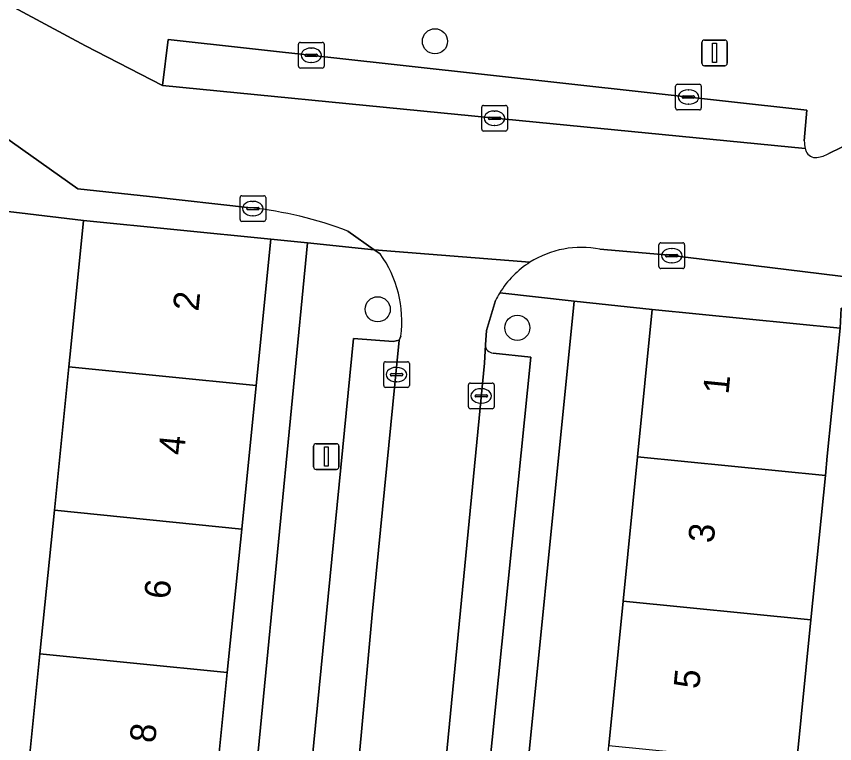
# Model space of a CAD drawing. Extents: x 162250 to 162661, y 380743 to 381606.
# Drawn here: x 162307.32 to 162339.15, y 380878.59 to 380906.87 of the extents above; entities that cross this region are included whole.
import ezdxf

# ---------------------------------------------------------------- set-up
doc = ezdxf.new("R2010")
doc.units = 0
for name, color, linetype in [('IMGEO_Boom', 7, 'Continuous'), ('IMGEO_Erf', 7, 'Continuous'), ('IMGEO_Kolk', 7, 'Continuous'), ('IMGEO_Lichtmast', 7, 'Continuous'), ('IMGEO_Muur', 7, 'Continuous'), ('IMGEO_Pand', 7, 'Continuous'), ('IMGEO_Pand_nummerreeks', 7, 'Continuous'), ('IMGEO_Parkeervlak_open', 7, 'Continuous'), ('IMGEO_Rijbaan_lokaal_open', 7, 'Continuous'), ('IMGEO_Rioolput', 7, 'Continuous'), ('IMGEO_Voetpad_open', 7, 'Continuous')]:
    doc.layers.add(name, color=color, linetype=linetype)

msp = doc.modelspace()

# ---------------------------------------------------------------- linework, layer by layer
at = {"layer": 'IMGEO_Boom'}
for centre in [(162323.604, 380905.904), (162321.376, 380895.484), (162326.808, 380894.764)]:
    msp.add_circle(centre, 0.489, dxfattribs=at)
at = {"layer": 'IMGEO_Erf'}
msp.add_lwpolyline([(162307.682, 380876.513), (162308.241, 380882.089), (162308.8, 380887.667), (162309.359, 380893.244), (162309.435, 380893.999), (162309.931, 380898.942), (162307.447, 380899.233), (162299.23, 380900.181), (162298.807, 380896.512), (162302.633, 380896.065), (162302.385, 380893.943), (162302.081, 380891.349), (162298.255, 380891.796), (162297.549, 380885.372), (162301.375, 380884.925), (162301.127, 380882.802), (162300.823, 380880.209), (162296.997, 380880.656), (162296.291, 380874.233)], dxfattribs=at)
for points in [[(162317.217, 380898.211), (162316.646, 380892.514), (162316.086, 380886.937), (162315.527, 380881.36), (162314.968, 380875.783), (162314.409, 380870.206), (162313.849, 380864.627), (162313.289, 380859.043), (162312.729, 380853.459), (162312.169, 380847.873), (162311.609, 380842.288), (162311.049, 380836.704), (162310.497, 380831.191), (162309.933, 380825.574), (162309.37, 380819.961), (162308.808, 380814.349), (162308.245, 380808.736), (162307.67, 380803.003), (162309.116, 380802.856), (162315.15, 380861.984), (162318.65, 380898.061)], [(162331.483, 380889.744), (162332.054, 380895.474), (162329.014, 380895.802), (162326.75, 380873.094), (162329.792, 380872.791), (162330.363, 380878.521), (162330.923, 380884.132)], [(162349.956, 380885.449), (162346.117, 380885.769), (162346.325, 380888.261), (162346.512, 380890.503), (162350.351, 380890.183), (162350.689, 380894.244), (162339.398, 380895.532), (162339.361, 380894.746), (162338.865, 380889.771), (162338.79, 380889.014), (162338.23, 380883.402), (162337.67, 380877.791), (162337.099, 380872.063), (162348.708, 380870.908), (162348.984, 380874.212), (162345.145, 380874.532), (162345.353, 380877.023), (162345.54, 380879.266), (162349.379, 380878.946)]]:
    msp.add_lwpolyline(points, close=True, dxfattribs=at)
at = {"layer": 'IMGEO_Kolk'}
for p, q in [((162318.294, 380904.936), (162318.294, 380905.788)), ((162318.369, 380905.862), (162319.221, 380905.862)), ((162319.295, 380905.788), (162319.295, 380904.936)), ((162318.782, 380905.642), (162318.807, 380905.642)), ((162318.553, 380905.356), (162318.553, 380905.368)), ((162318.991, 380905.319), (162318.593, 380905.319)), ((162318.596, 380905.405), (162318.994, 380905.405)), ((162319.037, 380905.368), (162319.037, 380905.356)), ((162319.221, 380904.862), (162318.369, 380904.862)), ((162318.805, 380905.082), (162318.78, 380905.082)), ((162333.036, 380904.237), (162333.888, 380904.237)), ((162332.961, 380903.311), (162332.961, 380904.163)), ((162333.449, 380904.017), (162333.474, 380904.017)), ((162333.962, 380904.163), (162333.962, 380903.311)), ((162333.22, 380903.731), (162333.22, 380903.743)), ((162333.658, 380903.694), (162333.26, 380903.694)), ((162333.263, 380903.78), (162333.661, 380903.78)), ((162333.704, 380903.743), (162333.704, 380903.731)), ((162333.888, 380903.237), (162333.036, 380903.237)), ((162333.472, 380903.457), (162333.447, 380903.457)), ((162316.022, 380898.974), (162316.022, 380899.826)), ((162316.097, 380899.9), (162316.949, 380899.9)), ((162317.023, 380899.826), (162317.023, 380898.974)), ((162316.281, 380899.394), (162316.281, 380899.406)), ((162316.324, 380899.443), (162316.722, 380899.443)), ((162316.51, 380899.68), (162316.535, 380899.68)), ((162316.765, 380899.406), (162316.765, 380899.394)), ((162316.719, 380899.357), (162316.321, 380899.357)), ((162316.533, 380899.12), (162316.508, 380899.12)), ((162316.949, 380898.9), (162316.097, 380898.9)), ((162332.314, 380897.143), (162332.314, 380897.995)), ((162332.389, 380898.069), (162333.241, 380898.069)), ((162332.802, 380897.849), (162332.827, 380897.849)), ((162333.315, 380897.995), (162333.315, 380897.143)), ((162332.573, 380897.563), (162332.573, 380897.575)), ((162333.011, 380897.526), (162332.613, 380897.526)), ((162332.616, 380897.612), (162333.014, 380897.612)), ((162333.057, 380897.575), (162333.057, 380897.563)), ((162332.825, 380897.289), (162332.8, 380897.289)), ((162333.241, 380897.069), (162332.389, 380897.069)), ((162321.609, 380892.517), (162321.609, 380893.369)), ((162321.684, 380893.443), (162322.536, 380893.443)), ((162322.61, 380893.369), (162322.61, 380892.517)), ((162322.097, 380893.223), (162322.122, 380893.223)), ((162321.868, 380892.937), (162321.868, 380892.949)), ((162322.306, 380892.9), (162321.908, 380892.9)), ((162321.911, 380892.986), (162322.309, 380892.986)), ((162322.352, 380892.949), (162322.352, 380892.937)), ((162322.536, 380892.443), (162321.684, 380892.443)), ((162322.12, 380892.663), (162322.095, 380892.663)), ((162324.905, 380891.689), (162324.905, 380892.541)), ((162324.98, 380892.615), (162325.832, 380892.615)), ((162325.393, 380892.395), (162325.418, 380892.395)), ((162325.906, 380892.541), (162325.906, 380891.689)), ((162325.164, 380892.109), (162325.164, 380892.121)), ((162325.602, 380892.072), (162325.204, 380892.072)), ((162325.207, 380892.158), (162325.605, 380892.158)), ((162325.648, 380892.121), (162325.648, 380892.109)), ((162325.416, 380891.835), (162325.391, 380891.835)), ((162325.832, 380891.615), (162324.98, 380891.615))]:
    msp.add_line(p, q, dxfattribs=at)
for points in [[(162318.294, 380904.936), (162318.294, 380905.788)], [(162318.369, 380905.862), (162319.221, 380905.862)], [(162319.295, 380905.788), (162319.295, 380904.936)], [(162319.221, 380904.862), (162318.369, 380904.862)], [(162333.036, 380904.237), (162333.888, 380904.237)], [(162332.961, 380903.311), (162332.961, 380904.163)], [(162333.962, 380904.163), (162333.962, 380903.311)], [(162333.888, 380903.237), (162333.036, 380903.237)], [(162316.022, 380898.974), (162316.022, 380899.826)], [(162316.097, 380899.9), (162316.949, 380899.9)], [(162317.023, 380899.826), (162317.023, 380898.974)], [(162316.949, 380898.9), (162316.097, 380898.9)], [(162332.314, 380897.143), (162332.314, 380897.995)], [(162332.389, 380898.069), (162333.241, 380898.069)], [(162333.315, 380897.995), (162333.315, 380897.143)], [(162333.241, 380897.069), (162332.389, 380897.069)], [(162321.609, 380892.517), (162321.609, 380893.369)], [(162321.684, 380893.443), (162322.536, 380893.443)], [(162322.61, 380893.369), (162322.61, 380892.517)], [(162322.536, 380892.443), (162321.684, 380892.443)], [(162324.905, 380891.689), (162324.905, 380892.541)], [(162324.98, 380892.615), (162325.832, 380892.615)], [(162325.906, 380892.541), (162325.906, 380891.689)], [(162325.832, 380891.615), (162324.98, 380891.615)]]:
    msp.add_lwpolyline(points, dxfattribs=at)
for centre, radius, start, end in [((162318.371, 380905.786), 0.0765, 91.552, 178.448), ((162318.371, 380905.786), 0.0765, 91.552, 178.448), ((162319.219, 380905.786), 0.0765, 1.552, 88.448), ((162319.219, 380905.786), 0.0765, 1.552, 88.448), ((162318.593, 380905.365), 0.0403, 85.8775, 175.7526), ((162318.59, 380905.355), 0.0366, 178.938, 274.7102), ((162318.994, 380905.362), 0.043, 264.8664, 352.4533), ((162318.998, 380905.367), 0.0386, 1.7309, 96.639), ((162318.371, 380904.938), 0.0765, 181.552, 268.448), ((162318.371, 380904.938), 0.0765, 181.552, 268.448), ((162319.219, 380904.938), 0.0765, 271.552, 358.448), ((162319.219, 380904.938), 0.0765, 271.552, 358.448), ((162333.038, 380904.161), 0.0765, 91.552, 178.448), ((162333.038, 380904.161), 0.0765, 91.552, 178.448), ((162333.886, 380904.161), 0.0765, 1.552, 88.448), ((162333.886, 380904.161), 0.0765, 1.552, 88.448), ((162333.26, 380903.74), 0.0403, 85.8775, 175.7526), ((162333.257, 380903.73), 0.0366, 178.938, 274.7102), ((162333.661, 380903.737), 0.043, 264.8664, 352.4533), ((162333.665, 380903.742), 0.0386, 1.7309, 96.639), ((162333.038, 380903.313), 0.0765, 181.552, 268.448), ((162333.038, 380903.313), 0.0765, 181.552, 268.448), ((162333.886, 380903.313), 0.0765, 271.552, 358.448), ((162333.886, 380903.313), 0.0765, 271.552, 358.448), ((162316.099, 380899.824), 0.0765, 91.552, 178.448), ((162316.099, 380899.824), 0.0765, 91.552, 178.448), ((162316.947, 380899.824), 0.0765, 1.552, 88.448), ((162316.947, 380899.824), 0.0765, 1.552, 88.448), ((162316.321, 380899.403), 0.0403, 85.8775, 175.7526), ((162316.318, 380899.393), 0.0366, 178.938, 274.7102), ((162316.722, 380899.4), 0.043, 264.8664, 352.4533), ((162316.726, 380899.405), 0.0386, 1.7309, 96.639), ((162316.099, 380898.976), 0.0765, 181.552, 268.448), ((162316.099, 380898.976), 0.0765, 181.552, 268.448), ((162316.947, 380898.976), 0.0765, 271.552, 358.448), ((162316.947, 380898.976), 0.0765, 271.552, 358.448), ((162332.391, 380897.993), 0.0765, 91.552, 178.448), ((162332.391, 380897.993), 0.0765, 91.552, 178.448), ((162333.239, 380897.993), 0.0765, 1.552, 88.448), ((162333.239, 380897.993), 0.0765, 1.552, 88.448), ((162332.613, 380897.572), 0.0403, 85.8775, 175.7526), ((162332.61, 380897.562), 0.0366, 178.938, 274.7102), ((162333.014, 380897.569), 0.043, 264.8664, 352.4533), ((162333.018, 380897.574), 0.0386, 1.7309, 96.639), ((162332.391, 380897.145), 0.0765, 181.552, 268.448), ((162332.391, 380897.145), 0.0765, 181.552, 268.448), ((162333.239, 380897.145), 0.0765, 271.552, 358.448), ((162333.239, 380897.145), 0.0765, 271.552, 358.448), ((162321.686, 380893.367), 0.0765, 91.552, 178.448), ((162321.686, 380893.367), 0.0765, 91.552, 178.448), ((162322.534, 380893.367), 0.0765, 1.552, 88.448), ((162322.534, 380893.367), 0.0765, 1.552, 88.448), ((162321.908, 380892.946), 0.0403, 85.8775, 175.7526), ((162321.905, 380892.936), 0.0366, 178.938, 274.7102), ((162322.309, 380892.943), 0.043, 264.8664, 352.4533), ((162322.313, 380892.948), 0.0386, 1.7309, 96.639), ((162321.686, 380892.519), 0.0765, 181.552, 268.448), ((162321.686, 380892.519), 0.0765, 181.552, 268.448), ((162322.534, 380892.519), 0.0765, 271.552, 358.448), ((162322.534, 380892.519), 0.0765, 271.552, 358.448), ((162324.982, 380892.539), 0.0765, 91.552, 178.448), ((162324.982, 380892.539), 0.0765, 91.552, 178.448), ((162325.83, 380892.539), 0.0765, 1.552, 88.448), ((162325.83, 380892.539), 0.0765, 1.552, 88.448), ((162325.204, 380892.118), 0.0403, 85.8775, 175.7526), ((162325.201, 380892.108), 0.0366, 178.938, 274.7102), ((162325.605, 380892.115), 0.043, 264.8664, 352.4533), ((162325.609, 380892.12), 0.0386, 1.7309, 96.639), ((162324.982, 380891.691), 0.0765, 181.552, 268.448), ((162324.982, 380891.691), 0.0765, 181.552, 268.448), ((162325.83, 380891.691), 0.0765, 271.552, 358.448), ((162325.83, 380891.691), 0.0765, 271.552, 358.448)]:
    msp.add_arc(centre, radius, start, end, dxfattribs=at)
for centre, major_axis, ratio, start_param, end_param in [((162318.781, 380905.362), (-0.387, 0.002), 0.722429, 4.712389, 7.853982), ((162318.806, 380905.362), (-0.39, 0.002), 0.717154, 1.570796, 4.712389), ((162333.448, 380903.737), (-0.387, 0.002), 0.722429, 4.712389, 7.853982), ((162333.473, 380903.737), (-0.39, 0.002), 0.717154, 1.570796, 4.712389), ((162316.509, 380899.4), (-0.387, 0.002), 0.722429, 4.712389, 7.853982), ((162316.534, 380899.4), (-0.39, 0.002), 0.717154, 1.570796, 4.712389), ((162332.801, 380897.569), (-0.387, 0.002), 0.722429, 4.712389, 7.853982), ((162332.826, 380897.569), (-0.39, 0.002), 0.717154, 1.570796, 4.712389), ((162322.096, 380892.943), (-0.387, 0.002), 0.722429, 4.712389, 7.853982), ((162322.121, 380892.943), (-0.39, 0.002), 0.717154, 1.570796, 4.712389), ((162325.392, 380892.115), (-0.387, 0.002), 0.722429, 4.712389, 7.853982), ((162325.417, 380892.115), (-0.39, 0.002), 0.717154, 1.570796, 4.712389)]:
    msp.add_ellipse(centre, major_axis=major_axis, ratio=ratio, start_param=start_param, end_param=end_param, dxfattribs=at)
at = {"layer": 'IMGEO_Lichtmast'}
for p, q in [((162333.984, 380905.055), (162333.984, 380905.855)), ((162333.984, 380905.855), (162333.984, 380905.055)), ((162334.084, 380905.955), (162334.874, 380905.955)), ((162334.874, 380905.955), (162334.084, 380905.955)), ((162334.974, 380905.855), (162334.974, 380905.055)), ((162334.974, 380905.055), (162334.974, 380905.855)), ((162334.874, 380904.955), (162334.084, 380904.955)), ((162334.084, 380904.955), (162334.874, 380904.955)), ((162318.981, 380890.256), (162319.771, 380890.256)), ((162319.771, 380890.256), (162318.981, 380890.256)), ((162318.881, 380889.356), (162318.881, 380890.156)), ((162318.881, 380890.156), (162318.881, 380889.356)), ((162319.871, 380890.156), (162319.871, 380889.356)), ((162319.871, 380889.356), (162319.871, 380890.156)), ((162319.771, 380889.256), (162318.981, 380889.256)), ((162318.981, 380889.256), (162319.771, 380889.256))]:
    msp.add_line(p, q, dxfattribs=at)
for points in [[(162334.404, 380905.83), (162334.554, 380905.83), (162334.554, 380905.08), (162334.404, 380905.08), (162334.404, 380905.83)], [(162319.301, 380890.131), (162319.451, 380890.131), (162319.451, 380889.381), (162319.301, 380889.381), (162319.301, 380890.131)]]:
    msp.add_lwpolyline(points, dxfattribs=at)
for centre, start, end in [((162334.084, 380905.855), 90, 180), ((162334.084, 380905.855), 90, 180), ((162334.874, 380905.855), 0, 90), ((162334.874, 380905.855), 360, 90), ((162334.084, 380905.055), 180, 270), ((162334.084, 380905.055), 180, 270), ((162334.874, 380905.055), 270, 0), ((162334.874, 380905.055), 270, 0), ((162318.981, 380890.156), 90, 180), ((162318.981, 380890.156), 90, 180), ((162319.771, 380890.156), 0, 90), ((162319.771, 380890.156), 360, 90), ((162318.981, 380889.356), 180, 270), ((162318.981, 380889.356), 180, 270), ((162319.771, 380889.356), 270, 0), ((162319.771, 380889.356), 270, 0)]:
    msp.add_arc(centre, 0.1, start, end, dxfattribs=at)
at = {"layer": 'IMGEO_Muur'}
msp.add_lwpolyline([(162309.931, 380898.942), (162307.447, 380899.233)], dxfattribs=at)
at = {"layer": 'IMGEO_Pand'}
for points in [[(162316.646, 380892.514), (162317.217, 380898.211), (162309.931, 380898.942), (162309.435, 380893.999), (162309.359, 380893.244)], [(162338.79, 380889.014), (162338.865, 380889.771), (162339.361, 380894.746), (162332.054, 380895.474), (162331.483, 380889.744)], [(162316.646, 380892.514), (162309.359, 380893.244), (162308.8, 380887.667), (162316.086, 380886.937)], [(162330.923, 380884.132), (162338.23, 380883.402), (162338.79, 380889.014), (162331.483, 380889.744)], [(162308.241, 380882.089), (162315.527, 380881.36), (162316.086, 380886.937), (162308.8, 380887.667)], [(162337.67, 380877.791), (162338.23, 380883.402), (162330.923, 380884.132), (162330.363, 380878.521), (162337.566, 380877.801)], [(162308.241, 380882.089), (162307.682, 380876.513), (162314.968, 380875.783), (162315.527, 380881.36)]]:
    msp.add_lwpolyline(points, close=True, dxfattribs=at)
at = {"layer": 'IMGEO_Parkeervlak_open'}
for points in [[(162313.223, 380905.978), (162313.006, 380904.183), (162323.827, 380903.117), (162338.006, 380901.74)], [(162337.968, 380902.03), (162338.073, 380903.225), (162313.223, 380905.978)], [(162316.769, 380839.988), (162317.589, 380847.669), (162318.936, 380861.173), (162319.937, 380870.429), (162320.053, 380871.499), (162320.276, 380873.933), (162321.165, 380883.616), (162322.208, 380894.288), (162321.981, 380894.236), (162320.433, 380894.347), (162315.17, 380840.746), (162316.236, 380840.651)], [(162325.569, 380894.099), (162325.529, 380893.393), (162323.609, 380873.614), (162323.565, 380873.159), (162323.26, 380870.111), (162321.48, 380852.317), (162320.213, 380838.831), (162319.086, 380828.026)], [(162319.819, 380828.412), (162320.821, 380828.279), (162325.066, 380871.015), (162325.189, 380872.449), (162327.336, 380893.62), (162325.864, 380893.781)]]:
    msp.add_lwpolyline(points, dxfattribs=at)
for centre, radius, start, end in [((162339.728, 380902.113), 1.762, 182.7044, 192.2259), ((162325.876, 380894.088), 0.308, 177.9999, 267.7026)]:
    msp.add_arc(centre, radius, start, end, dxfattribs=at)
at = {"layer": 'IMGEO_Rijbaan_lokaal_open'}
for points in [[(162338.006, 380901.74), (162323.827, 380903.117), (162313.006, 380904.183), (162310.012, 380905.728), (162306.705, 380907.505), (162306.458, 380907.638), (162292.66, 380909.267), (162283.046, 380910.457), (162280.022, 380910.745), (162279.515, 380906.391), (162284.013, 380905.94), (162289.869, 380905.312), (162300.415, 380904.048), (162304.299, 380903.584), (162305.327, 380903.261), (162309.716, 380900.169), (162312.494, 380899.87), (162316.431, 380899.429)], [(162330.019, 380897.82), (162332.717, 380897.582), (162341.28, 380896.536), (162344.512, 380898.048), (162344.722, 380898.057), (162344.942, 380898.106), (162345.487, 380898.034), (162345.711, 380898.004), (162349.392, 380897.594), (162353.19, 380897.171), (162354.653, 380897.008), (162356.902, 380896.747), (162359.977, 380896.391), (162363.506, 380895.982), (162371.445, 380895.078), (162371.558, 380895.065), (162372.076, 380899.395), (162371.702, 380899.436), (162370.473, 380899.572), (162349.29, 380902.174), (162342.74, 380902.947), (162341.803, 380902.935), (162338.929, 380901.541)], [(162320.215, 380898.526), (162321.245, 380897.797), (162327.3, 380897.311)], [(162327.3, 380897.311), (162321.245, 380897.797), (162321.467, 380897.64)], [(162325.602, 380894.662), (162325.956, 380895.821)], [(162322.274, 380894.435), (162322.208, 380894.288), (162321.165, 380883.616), (162320.276, 380873.933), (162323.609, 380873.614), (162325.529, 380893.393), (162325.569, 380894.099), (162325.602, 380894.662)]]:
    msp.add_lwpolyline(points, dxfattribs=at)
for centre, radius, start, end in [((162339.637, 380902.096), 1.669, 192.308, 196.4548), ((162338.411, 380901.795), 0.412, 204.5795, 276.6921), ((162338.254, 380902.787), 1.417, 278.2994, 298.4242), ((162314.876, 380884.534), 14.976, 69.1152, 84.0411), ((162329.298, 380894.153), 3.737, 78.8808, 122.3254), ((162317.892, 380895.036), 4.423, 352.1963, 36.0696), ((162329.302, 380894.153), 3.74, 122.3717, 148.2572), ((162329.852, 380893.854), 4.364, 148.7163, 153.207)]:
    msp.add_arc(centre, radius, start, end, dxfattribs=at)
at = {"layer": 'IMGEO_Rioolput'}
for p, q in [((162325.421, 380902.487), (162325.421, 380903.339)), ((162325.496, 380903.413), (162326.348, 380903.413)), ((162326.422, 380903.339), (162326.422, 380902.487)), ((162325.68, 380902.907), (162325.68, 380902.919)), ((162325.723, 380902.956), (162326.121, 380902.956)), ((162325.909, 380903.193), (162325.934, 380903.193)), ((162326.164, 380902.919), (162326.164, 380902.907)), ((162326.118, 380902.87), (162325.72, 380902.87)), ((162325.932, 380902.633), (162325.907, 380902.633)), ((162326.348, 380902.413), (162325.496, 380902.413))]:
    msp.add_line(p, q, dxfattribs=at)
for points in [[(162325.421, 380902.487), (162325.421, 380903.339)], [(162325.496, 380903.413), (162326.348, 380903.413)], [(162326.422, 380903.339), (162326.422, 380902.487)], [(162326.348, 380902.413), (162325.496, 380902.413)]]:
    msp.add_lwpolyline(points, dxfattribs=at)
for centre, radius, start, end in [((162325.498, 380903.337), 0.0765, 91.552, 178.448), ((162325.498, 380903.337), 0.0765, 91.552, 178.448), ((162326.346, 380903.337), 0.0765, 1.552, 88.448), ((162326.346, 380903.337), 0.0765, 1.552, 88.448), ((162325.72, 380902.916), 0.0403, 85.8775, 175.7526), ((162325.717, 380902.906), 0.0366, 178.938, 274.7102), ((162326.121, 380902.913), 0.043, 264.8664, 352.4533), ((162326.125, 380902.918), 0.0386, 1.7309, 96.639), ((162325.498, 380902.489), 0.0765, 181.552, 268.448), ((162325.498, 380902.489), 0.0765, 181.552, 268.448), ((162326.346, 380902.489), 0.0765, 271.552, 358.448), ((162326.346, 380902.489), 0.0765, 271.552, 358.448)]:
    msp.add_arc(centre, radius, start, end, dxfattribs=at)
for centre, major_axis, ratio, start_param, end_param in [((162325.908, 380902.913), (-0.387, 0.002), 0.722429, 4.712389, 7.853982), ((162325.933, 380902.913), (-0.39, 0.002), 0.717154, 1.570796, 4.712389)]:
    msp.add_ellipse(centre, major_axis=major_axis, ratio=ratio, start_param=start_param, end_param=end_param, dxfattribs=at)
at = {"layer": 'IMGEO_Voetpad_open'}
for points in [[(162306.705, 380907.505), (162310.012, 380905.728), (162313.006, 380904.183), (162313.223, 380905.978), (162338.073, 380903.225), (162337.968, 380902.03)], [(162276.17, 380906.721), (162275.776, 380902.864), (162279.391, 380902.457), (162286.663, 380901.629), (162288.657, 380901.4), (162297.266, 380900.407), (162299.23, 380900.181), (162307.447, 380899.233), (162309.931, 380898.942), (162317.217, 380898.211), (162318.65, 380898.061), (162321.245, 380897.797), (162320.215, 380898.526)], [(162316.431, 380899.429), (162312.494, 380899.87), (162309.716, 380900.169), (162305.327, 380903.261)], [(162338.929, 380901.541), (162341.803, 380902.935)], [(162321.467, 380897.64), (162321.245, 380897.797), (162318.65, 380898.061), (162315.15, 380861.984), (162309.116, 380802.856), (162307.67, 380803.003), (162304.675, 380803.303), (162304.586, 380801.49), (162303.194, 380779.303), (162308.908, 380778.975), (162310.692, 380795.269), (162311.999, 380795.147)], [(162359.977, 380896.391), (162356.902, 380896.747), (162354.653, 380897.008), (162353.19, 380897.171), (162349.392, 380897.594), (162345.711, 380898.004), (162345.487, 380898.034), (162344.942, 380898.106), (162344.722, 380898.057), (162344.512, 380898.048), (162341.28, 380896.536), (162332.717, 380897.582), (162330.019, 380897.82)], [(162320.998, 380797.044), (162321.244, 380801.577), (162321.509, 380803.901), (162319.92, 380804.066), (162319.973, 380805.135), (162326.556, 380871.147), (162326.75, 380873.094), (162329.014, 380895.802), (162326.122, 380896.12)], [(162326.122, 380896.12), (162329.014, 380895.802), (162332.054, 380895.474), (162339.361, 380894.746), (162339.398, 380895.532), (162350.689, 380894.244), (162352.616, 380894.024), (162360.529, 380893.122), (162363.777, 380892.751), (162363.588, 380891.303), (162370.925, 380890.808), (162372.396, 380890.715), (162376.294, 380890.554), (162376.355, 380891.934), (162376.358, 380891.994)], [(162325.956, 380895.821), (162325.602, 380894.662), (162325.569, 380894.099)], [(162316.236, 380840.651), (162315.17, 380840.746), (162320.433, 380894.347), (162321.981, 380894.236), (162322.208, 380894.288), (162322.274, 380894.435)], [(162325.864, 380893.781), (162327.336, 380893.62), (162325.189, 380872.449), (162325.066, 380871.015), (162320.821, 380828.279), (162319.819, 380828.412)]]:
    msp.add_lwpolyline(points, dxfattribs=at)
for centre, radius, start, end in [((162339.728, 380902.113), 1.762, 182.7044, 192.2259), ((162339.637, 380902.096), 1.669, 192.308, 196.4548), ((162338.411, 380901.795), 0.412, 204.5795, 276.6921), ((162338.254, 380902.787), 1.417, 278.2994, 298.4242), ((162314.876, 380884.534), 14.976, 69.1152, 84.0411), ((162329.298, 380894.153), 3.737, 78.8808, 122.3254), ((162317.892, 380895.036), 4.423, 352.1963, 36.0696), ((162329.302, 380894.153), 3.74, 122.3717, 148.2572), ((162329.852, 380893.854), 4.364, 148.7163, 153.207), ((162325.876, 380894.088), 0.308, 177.9999, 267.7026)]:
    msp.add_arc(centre, radius, start, end, dxfattribs=at)

# ---------------------------------------------------------------- texts
at = {"layer": 'IMGEO_Pand_nummerreeks'}
for s, rotation, p in [('2', 84.2738, (162314.402, 380895.386)), ('1', 84.3052, (162335.019, 380892.153)), ('4', 84.2738, (162313.84, 380889.788)), ('3', 84.3052, (162334.442, 380886.368)), ('6', 84.2738, (162313.279, 380884.187)), ('5', 84.3052, (162333.877, 380880.697)), ('8', 84.2738, (162312.717, 380878.591))]:
    msp.add_text(s, height=1, rotation=rotation, dxfattribs=at).set_placement(p)

doc.saveas('drawing.dxf')
